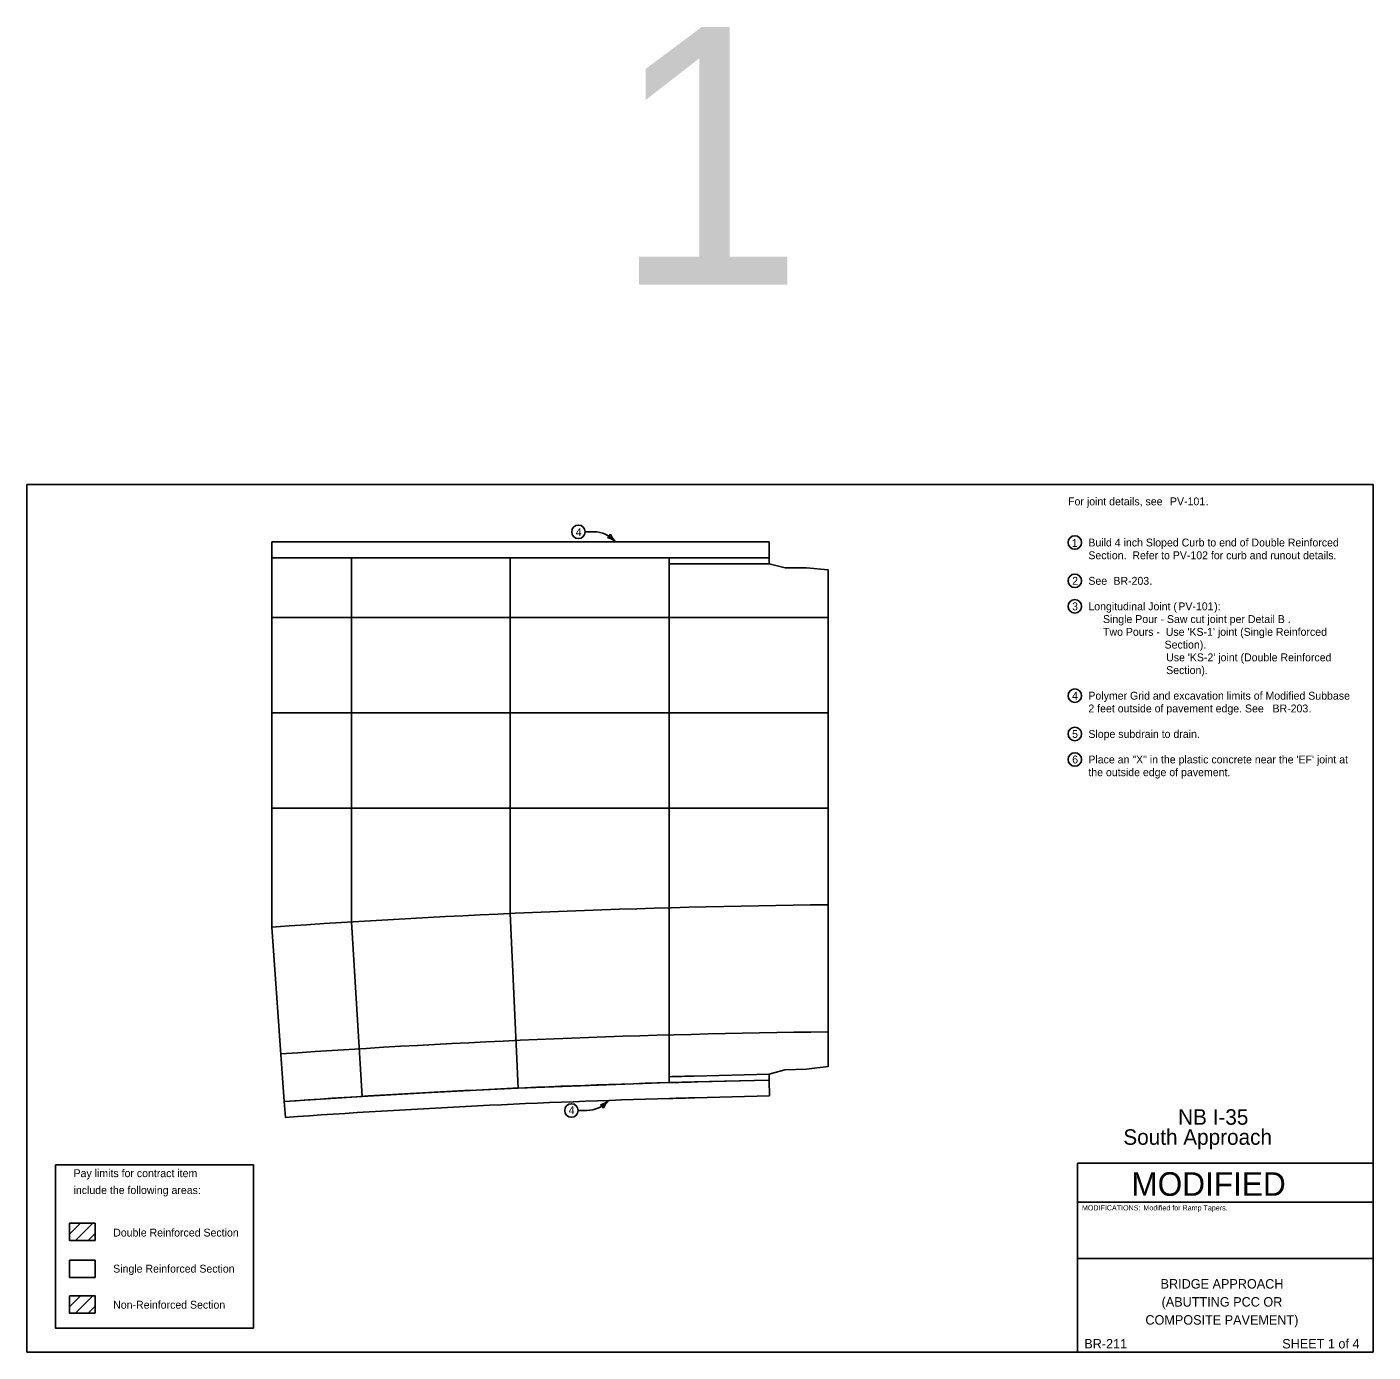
# Model space of a CAD drawing. Extents: x 10045 to 81668, y 6370 to 11018.
# Drawn here: x 10133 to 13268, y 7924 to 11009 of the extents above; entities that cross this region are included whole.
import ezdxf

# ---------------------------------------------------------------- set-up
doc = ezdxf.new("R2010")
doc.units = 0
for name, color, linetype in [('Alignment', 7, 'Continuous'), ('Bridge', 7, 'Continuous'), ('dsnStdLineWork', 7, 'Continuous'), ('LaneLine', 7, 'Continuous'), ('Level 5', 7, 'Continuous'), ('PC_APPROACH', 7, 'Continuous'), ('SheetText', 7, 'Continuous'), ('TextAlignmentLrg', 7, 'Continuous'), ('TextAlignmentSml', 7, 'Continuous')]:
    doc.layers.add(name, color=color, linetype=linetype)

msp = doc.modelspace()

# ---------------------------------------------------------------- linework, layer by layer
at = {"layer": 'Alignment'}
for p, q in [((11432.6, 9833.7), (11452.5, 9833.7)), ((11436.2, 8486.5), (11416.3, 8486.5)), ((10231.6, 8224.3), (10291.3, 8224.3)), ((10231.6, 8183.8), (10231.6, 8224.3)), ((10291.3, 8224.3), (10291.3, 8183.8)), ((10291.3, 8183.8), (10231.6, 8183.8)), ((10231.6, 8138.2), (10291.3, 8138.2)), ((10231.6, 8097.8), (10231.6, 8138.2)), ((10291.3, 8138.2), (10291.3, 8097.8)), ((10291.3, 8097.8), (10231.6, 8097.8))]:
    msp.add_line(p, q, dxfattribs=at)
for centre, start, end in [((11452.5, 9766.9), 40.5607, 90), ((11452.5, 9766.9), 40.5607, 90), ((11436.2, 8553.3), 270, 319.4393), ((11436.2, 8553.3), 270, 319.4393)]:
    msp.add_arc(centre, 66.8, start, end, dxfattribs=at)
at = {"layer": 'Bridge'}
for p, q in [((12579.5, 8272.7), (13267.5, 8272.7)), ((12579.5, 8142.2), (13267.5, 8142.2))]:
    msp.add_line(p, q, dxfattribs=at)
msp.add_lwpolyline([(12579.5, 8364), (13267.5, 8364), (13267.5, 7924), (12579.5, 7924)], close=True, dxfattribs=at)
at = {"layer": 'dsnStdLineWork'}
for p, q in [((11628.3, 9810.3), (10703.2, 9810.3)), ((10703.2, 9810.3), (10703.2, 9773.3)), ((11861.1, 9810.3), (11628.3, 9810.3)), ((11861.1, 9810.3), (11861.1, 9773.3)), ((10734.4, 8470.4), (10731.8, 8507.3)), ((11862, 8520.2), (11688.1, 8515.9)), ((10231.6, 8224.3), (10291.3, 8224.3)), ((10231.6, 8224.3), (10231.6, 8183.8)), ((10231.6, 8198.7), (10257.3, 8224.3)), ((10245.9, 8183.8), (10286.4, 8224.3)), ((10291.3, 8224.3), (10291.3, 8183.8)), ((10291.3, 8183.8), (10231.6, 8183.8)), ((10275, 8183.8), (10291.3, 8200.2)), ((10231.6, 8138.2), (10291.3, 8138.2)), ((10231.6, 8138.2), (10231.6, 8097.8)), ((10291.3, 8138.2), (10291.3, 8097.8)), ((10291.3, 8097.8), (10231.6, 8097.8)), ((10231.6, 8029.6), (10257.3, 8055.3)), ((10245.9, 8014.8), (10286.4, 8055.3)), ((10275, 8014.8), (10291.3, 8031.2))]:
    msp.add_line(p, q, dxfattribs=at)
for points in [[(11258.2, 9773.3), (10703.2, 9773.3), (10703.2, 8913.3), (10731.8, 8507.3), (10913.3, 8519.3), (11060.1, 8527.8), (11179.8, 8534.1), (11276.4, 8538.6), (11258.2, 8945.2)], [(11628.3, 9773.3), (11628.3, 8551.3), (11861.1, 8557.2), (11860.8, 8571.1), (11897.5, 8581.2), (11948, 8582.5), (11998.4, 8588.7), (11998.4, 9745.2), (11948.3, 9750.2), (11898.1, 9750.2), (11861.1, 9759.4), (11861.1, 9773.3)], [(10198.9, 8360.3), (10660.1, 8360.3), (10660.1, 7980), (10198.9, 7980)], [(10231.6, 8055.3), (10291.3, 8055.3), (10291.3, 8014.8), (10231.6, 8014.8)]]:
    msp.add_lwpolyline(points, close=True, dxfattribs=at)
msp.add_lwpolyline([(11862, 8520.2), (11862, 8520.2), (11861.1, 8557.2)], dxfattribs=at)
for centre in [(11416.9, 9833.7), (11416.9, 9833.7), (12573, 9808.8), (12573, 9719.6), (12573, 9660.2), (12573, 9452.2), (12573, 9363.1), (12573, 9303.7), (11400.6, 8486.5), (11400.6, 8486.5)]:
    msp.add_circle(centre, 15.7, dxfattribs=at)
for centre, radius, start, end in [((11475.9, 9835.6), 17.1, 299.4947, 334.9614), ((11475.9, 9835.6), 17.1, 299.4947, 334.9614), ((11473.1, 9777.7), 44.4, 47.2281, 75.3006), ((11473.1, 9777.7), 44.4, 47.2281, 75.3006), ((11533.4, 9842.9), 44.4, 199.1556, 227.2281), ((11533.4, 9842.9), 44.4, 199.1556, 227.2281), ((12213.6, -12506.9), 21029.4, 91.59218, 94.03365), ((11456.8, 8542.5), 44.4, 284.6994, 312.7719), ((11456.8, 8542.5), 44.4, 284.6994, 312.7719), ((11459.6, 8484.6), 17.1, 25.0386, 60.5053), ((11459.6, 8484.6), 17.1, 25.0386, 60.5053), ((11517.1, 8477.3), 44.4, 132.7719, 160.8444), ((11517.1, 8477.3), 44.4, 132.7719, 160.8444), ((12213.6, -12506.9), 21029.4, 91.4321, 91.59114)]:
    msp.add_arc(centre, radius, start, end, dxfattribs=at)
at = {"layer": 'LaneLine'}
msp.add_lwpolyline([(11258.2, 9773.3), (11258.2, 8945.2), (11276.4, 8538.6), (11628.3, 8551.3), (11861.1, 8557.2), (11860.8, 8571.1), (11897.5, 8581.2), (11948, 8582.5), (11998.4, 8588.7), (11998.4, 9745.2), (11948.3, 9750.2), (11898.1, 9750.2), (11861.1, 9759.4), (11861.1, 9773.3)], close=True, dxfattribs=at)
at = {"layer": 'Level 5'}
msp.add_lwpolyline([(10132.5, 9944), (13267.5, 9944), (13267.5, 7924), (10132.5, 7924)], close=True, dxfattribs=at)
at = {"layer": 'PC_APPROACH'}
for p, q in [((11628.3, 9773.3), (10703.2, 9773.3)), ((10703.2, 9773.3), (10703.2, 8913.3)), ((11861.1, 9759.4), (11861.1, 9773.3)), ((11998.4, 9745.2), (11998.4, 8588.7)), ((10731.8, 8507.3), (10703.2, 8913.3))]:
    msp.add_line(p, q, dxfattribs=at)
for points in [[(11998.4, 9745.2), (11948.3, 9750.2), (11898.1, 9750.2), (11861.1, 9759.4)], [(11861.1, 8557.2), (11860.8, 8571.1), (11897.5, 8581.2), (11948, 8582.5), (11998.4, 8588.7)]]:
    msp.add_lwpolyline(points, dxfattribs=at)
msp.add_arc((12213.6, -12506.9), 21066.4, 91.59218, 94.03365, dxfattribs=at)
at = {"layer": 'TextAlignmentLrg'}
for p, q in [((10888.2, 9773.3), (10888.2, 8925.6)), ((11258.2, 9773.3), (11258.2, 8945.2)), ((11628.3, 9773.3), (11628.3, 8551.3)), ((10703.2, 9634.2), (11998.3, 9634.2)), ((10703.2, 9412.1), (11998.3, 9412.1)), ((10703.2, 9190.1), (11998.3, 9190.1)), ((11276.4, 8538.6), (11258.2, 8945.2)), ((10913.3, 8519.3), (10888.2, 8925.6))]:
    msp.add_line(p, q, dxfattribs=at)
for radius, start in [(21473.4, 90.57462), (21177.4, 90.58243)]:
    msp.add_arc((12213.6, -12506.9), radius, start, 94.03365, dxfattribs=at)
at = {"layer": 'TextAlignmentSml'}
for p, q in [((11628.3, 9759.4), (11628.3, 9773.3)), ((11861.1, 9773.3), (11628.3, 9773.3)), ((11861.1, 9759.4), (11628.3, 9759.4)), ((11628.3, 8565.2), (11628.3, 8551.3)), ((11860.8, 8571.1), (11686.8, 8566.7)), ((11861.1, 8557.2), (11687.1, 8552.9))]:
    msp.add_line(p, q, dxfattribs=at)
for radius in [21080.2, 21066.4]:
    msp.add_arc((12213.6, -12506.9), radius, 91.4321, 91.59114, dxfattribs=at)

# ---------------------------------------------------------------- texts
at = {"layer": 'Alignment'}
for s, height, p in [('For joint details, see ', 18.375, (12557.3, 9895.4)), ('PV-101', 18.37, (12794.5, 9895.4)), ('PV-101', 18.37, (12794.5, 9895.4)), ('.', 18.4, (12877.7, 9895.4)), ('4', 18.4, (11410.5, 9823.8)), ('4', 18.4, (11410.5, 9823.8)), ('1', 18.4, (12565.8, 9798.5)), ('Build 4 inch Sloped Curb to end of Double Reinforced', 18.375, (12604.5, 9799.6)), ('Section.  Refer to PV-102 for curb and runout details.', 18.375, (12604.5, 9769.9)), ('2', 18.4, (12566.8, 9710.4)), ('See ', 18.37, (12604.5, 9710.4)), ('BR-203.', 18.37, (12662.8, 9710.4)), ('.', 18.4, (12747.4, 9710.4)), ('3', 18.4, (12566.6, 9651)), ('Longitudinal Joint (', 18.375, (12604.5, 9651)), ('PV-101', 18.37, (12814, 9651)), ('PV-101', 18.37, (12814, 9651)), ('):', 18.37, (12897.3, 9651)), ('     Single Pour - Saw cut joint per Detail B .', 18.375, (12604.5, 9621.3)), ("     Two Pours -  Use 'KS-1' joint (Single Reinforced", 18.375, (12604.5, 9591.6)), ('                          Section).', 18.375, (12604.5, 9561.9)), ("     Use 'KS-2' joint (Double Reinforced", 18.375, (12751.5, 9532.2)), ('     Section).', 18.375, (12751.5, 9502.5)), ('4', 18.4, (12566.6, 9443)), ('Polymer Grid and excavation limits of Modified Subbase', 18.375, (12604.5, 9443)), ('2 feet outside of pavement edge. See ', 18.375, (12604.5, 9413.3)), ('BR-203', 18.37, (13033.3, 9413.3)), ('.', 18.4, (13117.9, 9413.3)), ('5', 18.4, (12566.6, 9353.9)), ('Slope subdrain to drain.', 18.375, (12604.5, 9353.9)), ('6', 18.4, (12566.8, 9294.5)), ('Place an "X" in the plastic concrete near the \'EF\' joint at', 18.375, (12604.5, 9294.5)), ('the outside edge of pavement.', 18.375, (12604.5, 9264.8)), ('4', 18.4, (11394.1, 8478)), ('4', 18.4, (11394.1, 8478)), ('Pay limits for contract item', 18.375, (10241.1, 8331.3)), ('include the following areas:', 18.375, (10241.1, 8292)), ('Double Reinforced Section', 18.375, (10333.4, 8193)), ('Single Reinforced Section', 18.375, (10333.4, 8109)), ('Non-Reinforced Section', 18.375, (10333.4, 8025))]:
    msp.add_text(s, height=height, dxfattribs=at).set_placement(p)
at = {"layer": 'Bridge'}
for s, height, p in [('NB I-35', 36.09, (12813.5, 8453.3)), ('South Approach', 36.086, (12686, 8406.6)), ('MODIFIED', 55, (12704.6, 8287.8)), ('MODIFICATIONS:', 12, (12589.5, 8253.8)), ('Modified for Ramp Tapers.', 12, (12732.7, 8253.8)), ('BRIDGE APPROACH', 22, (12772.7, 8071.9)), ('(ABUTTING PCC OR', 22, (12775, 8029.9)), ('COMPOSITE PAVEMENT)', 22, (12737.3, 7987.9)), ('BR-211', 22, (12595, 7932.4)), ('SHEET 1 of 4', 22, (13056, 7932.4))]:
    msp.add_text(s, height=height, dxfattribs=at).set_placement(p)
at = {"layer": 'SheetText'}
msp.add_text('1', height=600, dxfattribs=at).set_placement((11496.6, 10409.2))

doc.saveas('drawing.dxf')
